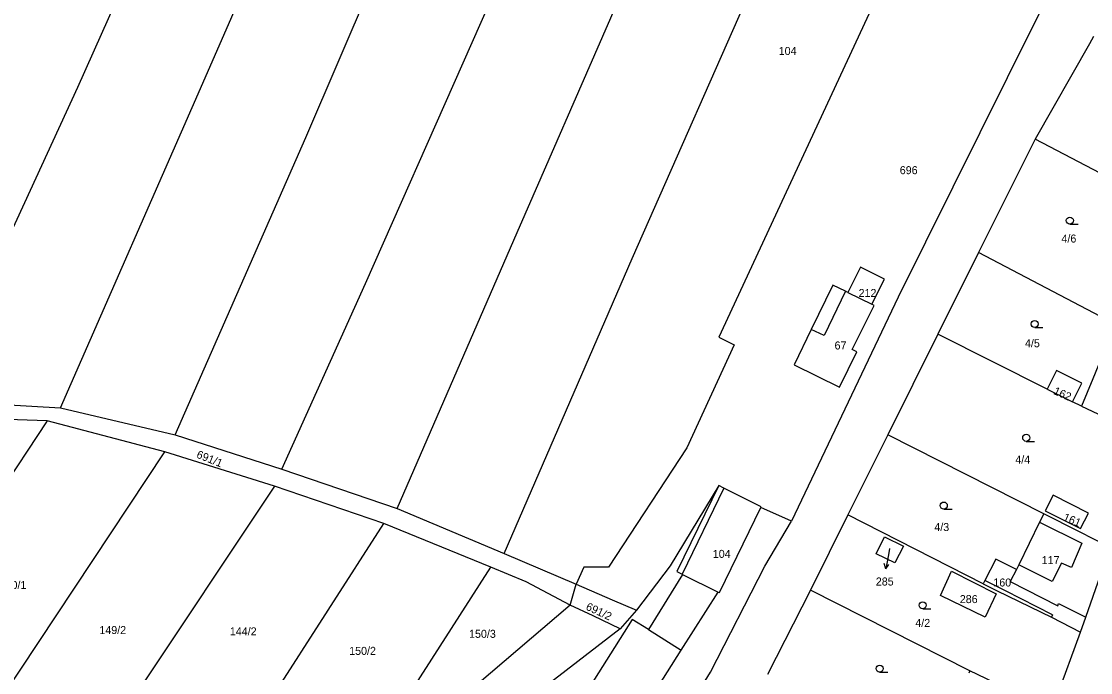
# Model space of a CAD drawing. Extents: x -7483133 to -743907, y -11317770 to -1129777.
# Drawn here: x -746337 to -746109.8, y -1131600.2 to -1131461.9 of the extents above; entities that cross this region are included whole.
import ezdxf

# ---------------------------------------------------------------- set-up
doc = ezdxf.new("R2010")
doc.units = 0
for name, color, linetype in [('Hranice parcel', 7, 'Continuous'), ('Parcelní čísla', 7, 'Continuous'), ('Pop  PČ popisy', 7, 'Continuous'), ('Vnitřní kresba', 7, 'Continuous'), ('Značky kultur', 7, 'Continuous')]:
    doc.layers.add(name, color=color, linetype=linetype)

msp = doc.modelspace()

# ---------------------------------------------------------------- linework, layer by layer
at = {"layer": 'Hranice parcel'}
for p, q in [((-746121.6, -1131486.86), (-746133.59, -1131510.98)), ((-746101.76, -1131497.26), (-746121.6, -1131486.86)), ((-746133.59, -1131510.98), (-746142.23, -1131528.33)), ((-746106.2, -1131525.3), (-746133.59, -1131510.98)), ((-746161.36, -1131519.45), (-746156.25, -1131521.97)), ((-746142.23, -1131528.33), (-746152.87, -1131549.67)), ((-746119.01, -1131540), (-746142.23, -1131528.33)), ((-746119.01, -1131540), (-746113.64, -1131542.65)), ((-746355.61, -1131542.43), (-746328.65, -1131543.97)), ((-746328.65, -1131543.97), (-746304.3, -1131549.68)), ((-746111.71, -1131543.57), (-746113.64, -1131542.65)), ((-746111.71, -1131543.57), (-746096.91, -1131550.67)), ((-746331.46, -1131546.72), (-746359.57, -1131545.85)), ((-746331.46, -1131546.72), (-746366.12, -1131598.98)), ((-746306.49, -1131553.28), (-746331.46, -1131546.72)), ((-746304.3, -1131549.68), (-746281.63, -1131556.99)), ((-746152.87, -1131549.67), (-746161.36, -1131566.66)), ((-746119.76, -1131566.48), (-746152.87, -1131549.67)), ((-746348.04, -1131615.98), (-746306.49, -1131553.28)), ((-746283.17, -1131560.59), (-746306.49, -1131553.28)), ((-746281.63, -1131556.99), (-746257.15, -1131565.35)), ((-746283.17, -1131560.59), (-746323.97, -1131621.69)), ((-746259.92, -1131568.5), (-746283.17, -1131560.59)), ((-746257.15, -1131565.35), (-746234.36, -1131574.92)), ((-746173.33, -1131568.01), (-746179.87, -1131565.13)), ((-746161.36, -1131566.66), (-746169.3, -1131582.67)), ((-746132.61, -1131581.31), (-746161.36, -1131566.66)), ((-746293.31, -1131620.35), (-746259.92, -1131568.5)), ((-746237.25, -1131577.76), (-746259.92, -1131568.5)), ((-746110.85, -1131588.4), (-746105.62, -1131573.59)), ((-746234.36, -1131574.92), (-746219.1, -1131581.44)), ((-746196.48, -1131579.32), (-746188.95, -1131583.07)), ((-746220.35, -1131585.87), (-746219.1, -1131581.44)), ((-746169.3, -1131582.67), (-746178.46, -1131600.58)), ((-746135.43, -1131599.84), (-746169.3, -1131582.67)), ((-746206.27, -1131586.91), (-746209.75, -1131590.87)), ((-746111.97, -1131591.58), (-746110.85, -1131588.4)), ((-746209.75, -1131590.87), (-746226.17, -1131603.55)), ((-746118.15, -1131608.57), (-746111.97, -1131591.58)), ((-746135.43, -1131599.84), (-746135.65, -1131600.29))]:
    msp.add_line(p, q, dxfattribs=at)
for points in [[(-746355.61, -1131542.43), (-746324.93, -1131475.84), (-746303.11, -1131426.75), (-746270.15, -1131349.38), (-746250.49, -1131305.53)], [(-746328.65, -1131543.97), (-746298.39, -1131474.98), (-746247.6, -1131358.82), (-746226.99, -1131313.72)], [(-746304.3, -1131549.68), (-746276.49, -1131486.57), (-746241.74, -1131405.49), (-746204.37, -1131321.72)], [(-746281.63, -1131556.99), (-746263.86, -1131517.53), (-746222.34, -1131423.75), (-746209.5, -1131392.92), (-746191.95, -1131352.1), (-746181.58, -1131329.92)], [(-746257.15, -1131565.35), (-746231.61, -1131506.69), (-746191.8, -1131415.47), (-746175.11, -1131375.93), (-746157.27, -1131340.24)], [(-746234.36, -1131574.92), (-746207.21, -1131512.24), (-746179.95, -1131450.43), (-746151.42, -1131384.21), (-746133.83, -1131347.95)], [(-746111.08, -1131353.49), (-746143.06, -1131430.4), (-746188.77, -1131528.95), (-746185.55, -1131530.56), (-746195.61, -1131552.43), (-746212.24, -1131577.79), (-746217.48, -1131577.79), (-746219.1, -1131581.44)], [(-746090.75, -1131400.54), (-746121.73, -1131462.2), (-746150.71, -1131520.43), (-746173.33, -1131568.01)], [(-746109.2, -1131465.08), (-746110.05, -1131466.67), (-746121.6, -1131486.86)], [(-746156.25, -1131521.97), (-746153.61, -1131516.62), (-746158.72, -1131514.09), (-746161.36, -1131519.45)], [(-746161.36, -1131519.45), (-746161.85, -1131519.21), (-746164.57, -1131517.87), (-746169.15, -1131527.29), (-746172.8, -1131534.8)], [(-746172.8, -1131534.8), (-746163.15, -1131539.55), (-746159.49, -1131532.04), (-746160.43, -1131531.58), (-746155.77, -1131522.21), (-746156.25, -1131521.97)], [(-746104.53, -1131526.13), (-746105.42, -1131528.29), (-746109.33, -1131537.8), (-746111.71, -1131543.57)], [(-746113.64, -1131542.65), (-746111.67, -1131538.68), (-746117.05, -1131536.03), (-746119.01, -1131540)], [(-746188.81, -1131560.47), (-746199.16, -1131577.52), (-746206.27, -1131586.91)], [(-746188.81, -1131560.47), (-746197.69, -1131578.71), (-746196.61, -1131579.25), (-746196.48, -1131579.32)], [(-746179.87, -1131565.13), (-746179.8, -1131564.99), (-746187.32, -1131561.22), (-746187.73, -1131561.01), (-746188.81, -1131560.47)], [(-746110.28, -1131566.3), (-746117.75, -1131562.51), (-746119.43, -1131565.83), (-746111.97, -1131569.59), (-746110.28, -1131566.3)], [(-746188.95, -1131583.07), (-746188.68, -1131583.2), (-746179.87, -1131565.13)], [(-746119.76, -1131566.48), (-746120.65, -1131568.25), (-746125.06, -1131577.32), (-746125.58, -1131578.32)], [(-746105.62, -1131573.59), (-746112.3, -1131570.23), (-746119.76, -1131566.48)], [(-746221.25, -1131649.38), (-746209.49, -1131630.87), (-746190.58, -1131600.07), (-746179.04, -1131577.6), (-746173.33, -1131568.01)], [(-746149.58, -1131573.32), (-746151.37, -1131576.9), (-746155.37, -1131574.98), (-746153.62, -1131571.37), (-746149.58, -1131573.32)], [(-746125.58, -1131578.32), (-746129.97, -1131576.1), (-746132.28, -1131580.66), (-746132.61, -1131581.31)], [(-746260.07, -1131614.14), (-746256.36, -1131607.58), (-746237.25, -1131577.76)], [(-746220.35, -1131585.87), (-746229.75, -1131580.92), (-746237.25, -1131577.76)], [(-746125.58, -1131578.32), (-746126.87, -1131580.87), (-746116.8, -1131585.98), (-746116.6, -1131585.54), (-746110.85, -1131588.4)], [(-746196.48, -1131579.32), (-746203.74, -1131591.04), (-746207.17, -1131588.88), (-746236.19, -1131634.81), (-746225.82, -1131641.41)], [(-746129.84, -1131583.45), (-746132.21, -1131588.4), (-746141.73, -1131583.83), (-746139.39, -1131578.66), (-746129.84, -1131583.45)], [(-746219.1, -1131581.44), (-746211.45, -1131584.7), (-746206.27, -1131586.91)], [(-746132.61, -1131581.31), (-746129.63, -1131582.82), (-746118.13, -1131588.43), (-746111.97, -1131591.58)], [(-746225.82, -1131641.41), (-746196.77, -1131595.45), (-746188.95, -1131583.07)], [(-746220.35, -1131585.87), (-746245.48, -1131607.32), (-746260.07, -1131614.14)], [(-746209.75, -1131590.87), (-746215.49, -1131588.16), (-746220.35, -1131585.87)], [(-746118.15, -1131608.57), (-746124.96, -1131604.86), (-746135.43, -1131599.84)]]:
    msp.add_lwpolyline(points, dxfattribs=at)
at = {"layer": 'Pop  PČ popisy'}
for p, q in [((-746152.5, -1131573.86), (-746152.76, -1131575.18)), ((-746152.76, -1131575.18), (-746153.33, -1131578.13)), ((-746153.33, -1131578.13), (-746153.63, -1131577.05)), ((-746153.33, -1131578.13), (-746152.65, -1131577.24))]:
    msp.add_line(p, q, dxfattribs=at)
at = {"layer": 'Vnitřní kresba'}
for p, q in [((-746161.85, -1131519.21), (-746166.42, -1131528.62)), ((-746166.42, -1131528.62), (-746169.15, -1131527.29)), ((-746187.73, -1131561.01), (-746196.61, -1131579.25)), ((-746120.65, -1131568.25), (-746111.65, -1131572.71)), ((-746111.65, -1131572.71), (-746113.9, -1131577.84)), ((-746117.98, -1131580.83), (-746125.06, -1131577.32)), ((-746115.99, -1131576.95), (-746117.98, -1131580.83)), ((-746113.9, -1131577.84), (-746115.99, -1131576.95)), ((-746127.92, -1131582.84), (-746132.28, -1131580.66)), ((-746117.87, -1131587.95), (-746127.92, -1131582.84)), ((-746117.87, -1131587.95), (-746118.13, -1131588.43)), ((-746203.74, -1131591.04), (-746196.77, -1131595.45))]:
    msp.add_line(p, q, dxfattribs=at)
at = {"layer": 'Značky kultur'}
for p, q in [((-746114.22, -1131504.94), (-746112.47, -1131504.94)), ((-746121.69, -1131526.89), (-746119.94, -1131526.89)), ((-746123.49, -1131551.07), (-746121.74, -1131551.07)), ((-746141, -1131565.46), (-746139.25, -1131565.46)), ((-746145.48, -1131586.64), (-746143.73, -1131586.64)), ((-746154.62, -1131600.09), (-746152.87, -1131600.09))]:
    msp.add_line(p, q, dxfattribs=at)
for centre in [(-746114.22, -1131504.19), (-746121.69, -1131526.14), (-746123.49, -1131550.32), (-746141, -1131564.71), (-746145.48, -1131585.89), (-746154.62, -1131599.34)]:
    msp.add_circle(centre, 0.75, dxfattribs=at)

# ---------------------------------------------------------------- texts
at = {"layer": 'Parcelní čísla'}
for s, p in [('104', (-746176.07, -1131469.01)), ('696', (-746150.35, -1131494.33)), ('4/6', (-746116, -1131508.85)), ('212', (-746159.1, -1131520.42)), ('67', (-746164.2, -1131531.56)), ('4/5', (-746123.75, -1131531.09)), ('4/4', (-746125.8, -1131555.79)), ('4/3', (-746143.01, -1131570.12)), ('104', (-746190.07, -1131575.82)), ('117', (-746120.2, -1131577.15)), ('150/1', (-746341.58, -1131582.43)), ('285', (-746155.44, -1131581.69)), ('160', (-746130.47, -1131581.9)), ('286', (-746137.6, -1131585.43)), ('4/2', (-746147.05, -1131590.49)), ('149/2', (-746320.39, -1131592)), ('144/2', (-746292.67, -1131592.28)), ('150/3', (-746241.85, -1131592.8)), ('150/2', (-746267.32, -1131596.42))]:
    msp.add_text(s, height=1.7, dxfattribs=at).set_placement(p)
for s, rotation, p in [('162', 336, (-746117.85, -1131540.97)), ('691/1', 338, (-746299.9, -1131554.49)), ('161', 337, (-746115.79, -1131567.8)), ('691/2', 335, (-746217.19, -1131586.76))]:
    msp.add_text(s, height=1.7, rotation=rotation, dxfattribs=at).set_placement(p)

doc.saveas('drawing.dxf')
